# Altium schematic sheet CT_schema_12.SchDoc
size 389 x 385 mm
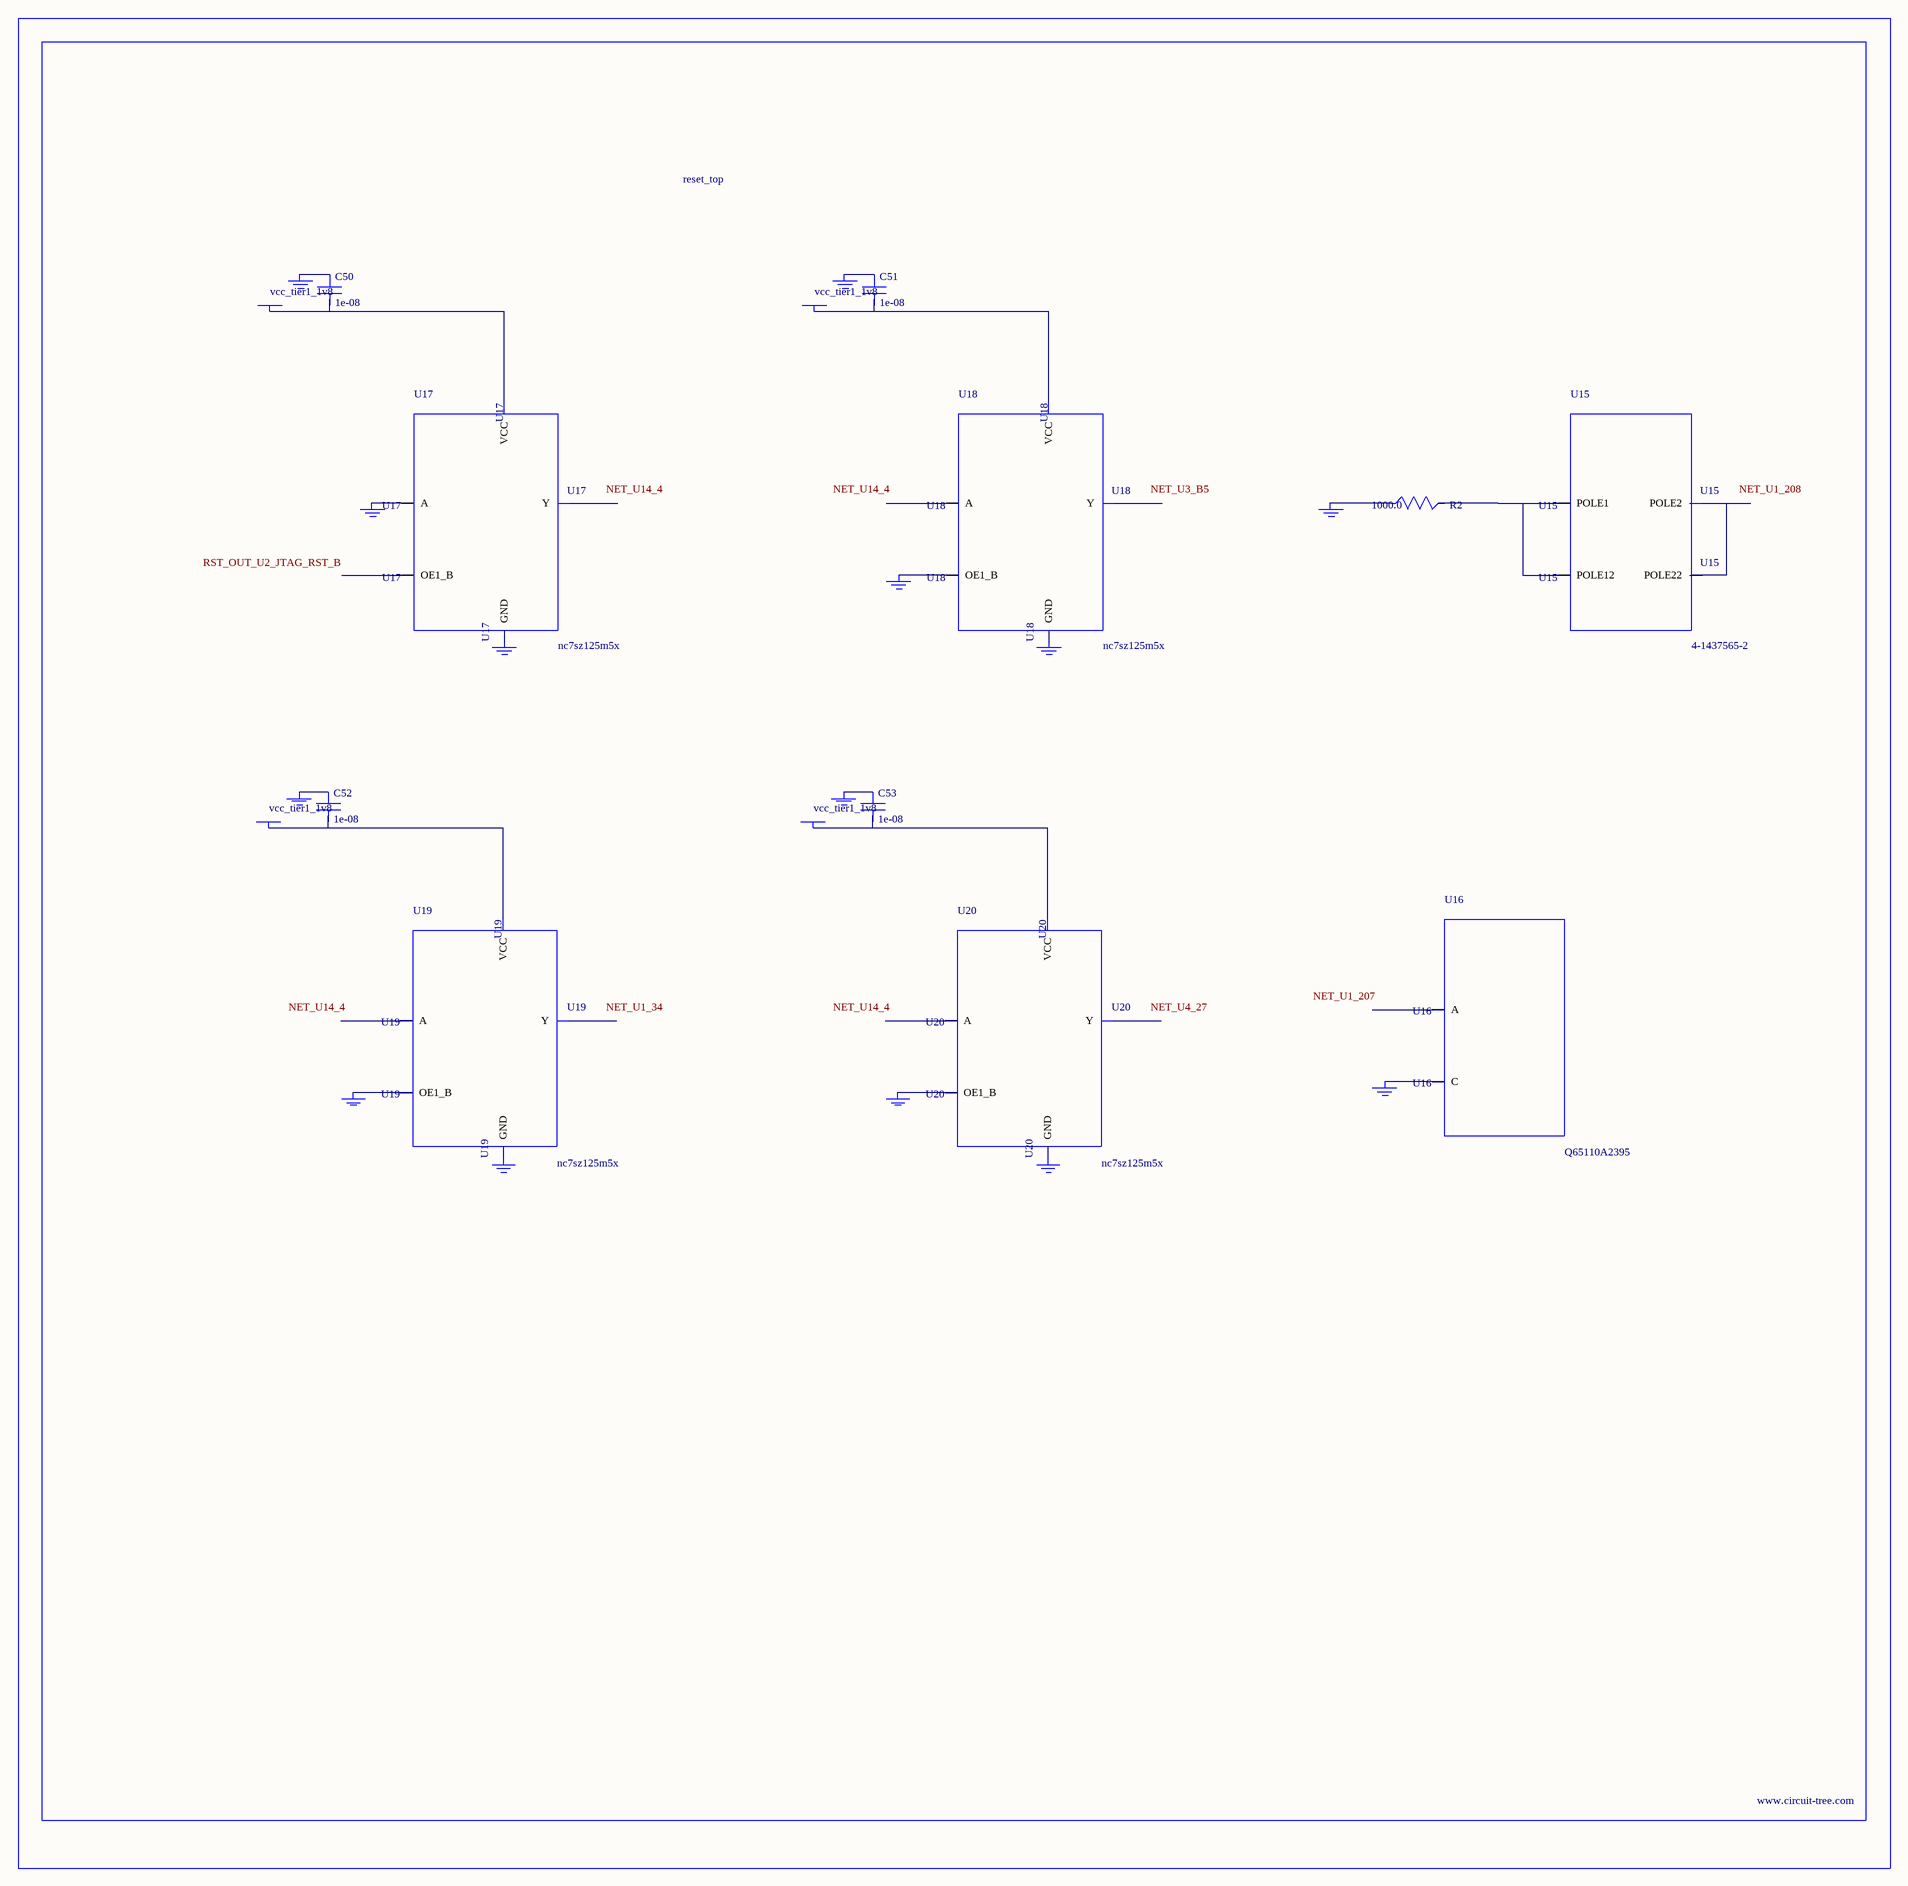
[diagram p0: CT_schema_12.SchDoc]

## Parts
BORDER11  (no value)
C50  1e-08  [C0402]
C51  1e-08  [C0402]
C52  1e-08  [C0402]
C53  1e-08  [C0402]
GND_INSTANCE_11_0  (no value)
GND_INSTANCE_11_1  (no value)
GND_INSTANCE_11_2  (no value)
GND_INSTANCE_11_3  (no value)
GND_INSTANCE_11_4  (no value)
GND_INSTANCE_11_5  (no value)
GND_INSTANCE_11_6  (no value)
GND_INSTANCE_11_7  (no value)
GND_INSTANCE_11_8  (no value)
GND_INSTANCE_11_9  (no value)
GND_INSTANCE_11_10  (no value)
GND_INSTANCE_11_11  (no value)
GND_INSTANCE_11_12  (no value)
GND_INSTANCE_11_13  (no value)
POWER_INSTANCE_11_0  vcc_tier1_1v8
POWER_INSTANCE_11_1  vcc_tier1_1v8
POWER_INSTANCE_11_2  vcc_tier1_1v8
POWER_INSTANCE_11_3  vcc_tier1_1v8
R2  1000.0  [R0603]
U15  4-1437565-2  [SW_4-1437565-2]
U16  Q65110A2395  [LGM67K-G1J2-24-Z]
U17  nc7sz125m5x  [NC7SZ125M5X]
U18  nc7sz125m5x  [NC7SZ125M5X]
U19  nc7sz125m5x  [NC7SZ125M5X]
U20  nc7sz125m5x  [NC7SZ125M5X]

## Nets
NetC50_1: C50.1 GND_INSTANCE_11_2.0(GND)
NetC50_2: C50.2 POWER_INSTANCE_11_0.0(PWR) U17.5(VCC)
NetC51_1: C51.1 GND_INSTANCE_11_5.0(GND)
NetC51_2: C51.2 POWER_INSTANCE_11_1.0(PWR) U18.5(VCC)
NetC52_1: C52.1 GND_INSTANCE_11_8.0(GND)
NetC52_2: C52.2 POWER_INSTANCE_11_2.0(PWR) U19.5(VCC)
NetC53_1: C53.1 GND_INSTANCE_11_11.0(GND)
NetC53_2: C53.2 POWER_INSTANCE_11_3.0(PWR) U20.5(VCC)
NetGND_INSTANCE_11_0_0: GND_INSTANCE_11_0.0(GND) R2.1
NetGND_INSTANCE_11_1_0: GND_INSTANCE_11_1.0(GND) U16.C
NetGND_INSTANCE_11_3_0: GND_INSTANCE_11_3.0(GND) U17.2(A)
NetGND_INSTANCE_11_4_0: GND_INSTANCE_11_4.0(GND) U17.3(GND)
NetGND_INSTANCE_11_6_0: GND_INSTANCE_11_6.0(GND) U18.1(OE1_B)
NetGND_INSTANCE_11_7_0: GND_INSTANCE_11_7.0(GND) U18.3(GND)
NetGND_INSTANCE_11_9_0: GND_INSTANCE_11_9.0(GND) U19.1(OE1_B)
NetGND_INSTANCE_11_10_0: GND_INSTANCE_11_10.0(GND) U19.3(GND)
NetGND_INSTANCE_11_12_0: GND_INSTANCE_11_12.0(GND) U20.1(OE1_B)
NetGND_INSTANCE_11_13_0: GND_INSTANCE_11_13.0(GND) U20.3(GND)
NetR2_2: R2.2 U15.1(POLE1) U15.2(POLE12)
NetU15_3: U15.3(POLE2) U15.4(POLE22)

Not connected (* = marked no-connect by the designer): U16 A; U17 1(OE1_B) 4(Y); U18 2(A) 4(Y); U19 2(A) 4(Y); U20 2(A) 4(Y)

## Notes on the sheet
- Labels drawn without touching a wire or pin: NET_U1_34, NET_U1_207, NET_U1_208, NET_U3_B5, NET_U4_27, NET_U14_4, RST_OUT_U2_JTAG_RST_B

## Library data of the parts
BORDER11 = BORDER_PAGE11
C50-C53 = C0402C103K3RAC
GND_INSTANCE_11_0-GND_INSTANCE_11_13 = GND
POWER_INSTANCE_11_0-POWER_INSTANCE_11_3 = PWR
R2 = RC0603JR-071KL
